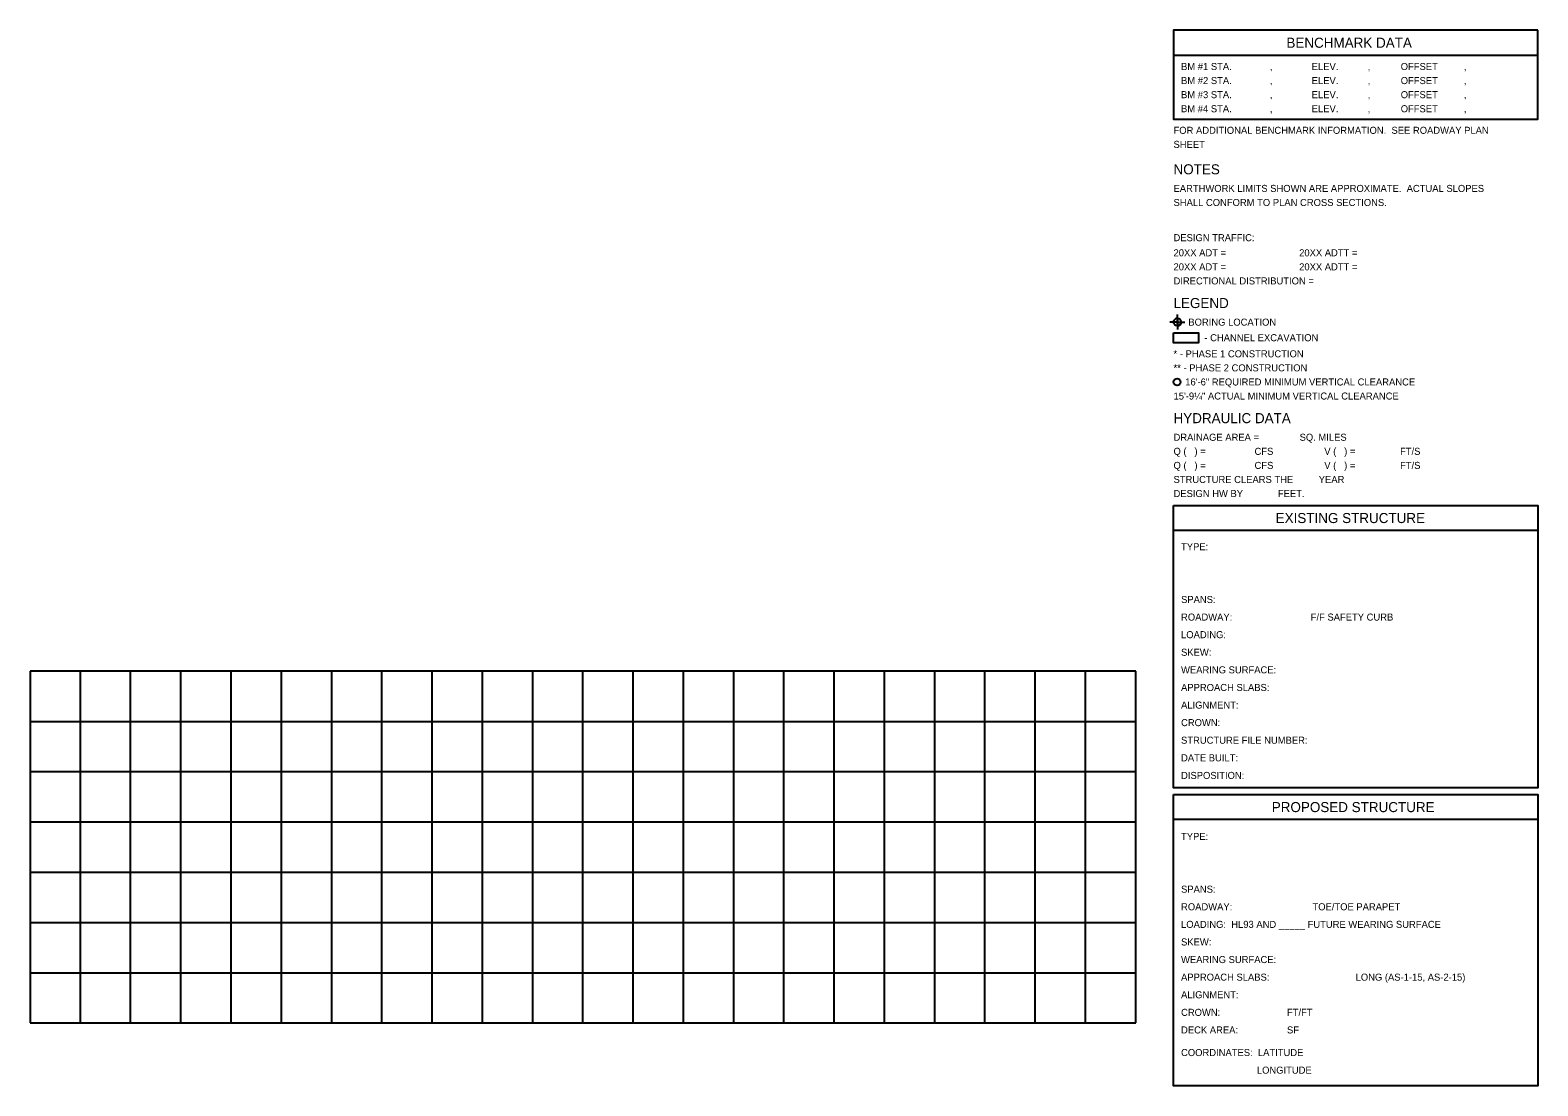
# Model space of a CAD drawing. Extents: x 0 to 112, y 0 to 22.
# Drawn here: x 81.7 to 111.7, y 0.5 to 21.5 of the extents above; entities that cross this region are included whole.
import ezdxf

# ---------------------------------------------------------------- set-up
doc = ezdxf.new("R2010")
doc.units = 0
for name, color, linetype in [('GT_Project_Soil_Boring', 7, 'Continuous'), ('SH_Data', 7, 'Continuous'), ('SH_Major_Grid_Line', 7, 'Continuous')]:
    doc.layers.add(name, color=color, linetype=linetype)

msp = doc.modelspace()

# ---------------------------------------------------------------- linework, layer by layer
at = {"layer": 'GT_Project_Soil_Boring'}
for p, q in [((104.529, 15.693), (104.379, 15.693)), ((104.529, 15.693), (104.454, 15.693)), ((104.529, 15.693), (104.529, 15.843)), ((104.529, 15.768), (104.529, 15.693)), ((104.529, 15.693), (104.529, 15.543)), ((104.529, 15.693), (104.679, 15.693)), ((104.529, 15.618), (104.529, 15.693)), ((104.529, 15.693), (104.604, 15.693))]:
    msp.add_line(p, q, dxfattribs=at)
msp.add_circle((104.529, 15.693), 0.075, dxfattribs=at)
for start, end in [(90, 180), (270, 360)]:
    msp.add_arc((104.529, 15.693), 0.075, start, end, dxfattribs=at)
at = {"layer": 'SH_Data'}
for p, q in [((104.452, 21), (111.702, 21)), ((111.702, 11.545), (104.452, 11.545)), ((81.7, 8.75), (81.7, 1.75)), ((103.7, 8.75), (81.7, 8.75)), ((103.7, 1.75), (103.7, 8.75)), ((111.702, 5.795), (104.452, 5.795)), ((81.7, 1.75), (103.7, 1.75))]:
    msp.add_line(p, q, dxfattribs=at)
for points in [[(111.702, 21.5), (104.452, 21.5), (104.452, 19.727), (111.702, 19.727)], [(104.452, 15.482), (104.952, 15.482), (104.952, 15.282), (104.452, 15.282)], [(104.452, 12.045), (111.702, 12.045), (111.702, 6.431), (104.452, 6.431)], [(104.452, 6.295), (111.702, 6.295), (111.702, 0.5), (104.452, 0.5)]]:
    msp.add_lwpolyline(points, close=True, dxfattribs=at)
msp.add_circle((104.522, 14.501), 0.07, dxfattribs=at)
at = {"layer": 'SH_Major_Grid_Line'}
for p, q in [((82.7, 1.75), (82.7, 8.75)), ((83.7, 1.75), (83.7, 8.75)), ((84.7, 1.75), (84.7, 8.75)), ((85.7, 1.75), (85.7, 8.75)), ((86.7, 1.75), (86.7, 8.75)), ((87.7, 1.75), (87.7, 8.75)), ((88.7, 1.75), (88.7, 8.75)), ((89.7, 1.75), (89.7, 8.75)), ((90.7, 1.75), (90.7, 8.75)), ((91.7, 1.75), (91.7, 8.75)), ((92.7, 1.75), (92.7, 8.75)), ((93.7, 1.75), (93.7, 8.75)), ((94.7, 1.75), (94.7, 8.75)), ((95.7, 1.75), (95.7, 8.75)), ((96.7, 1.75), (96.7, 8.75)), ((97.7, 1.75), (97.7, 8.75)), ((98.7, 1.75), (98.7, 8.75)), ((99.7, 1.75), (99.7, 8.75)), ((100.7, 1.75), (100.7, 8.75)), ((101.7, 1.75), (101.7, 8.75)), ((102.7, 1.75), (102.7, 8.75)), ((81.7, 7.75), (103.7, 7.75)), ((81.7, 6.75), (103.7, 6.75)), ((81.7, 5.75), (103.7, 5.75)), ((81.7, 4.75), (103.7, 4.75)), ((81.7, 3.75), (103.7, 3.75)), ((81.7, 2.75), (103.7, 2.75))]:
    msp.add_line(p, q, dxfattribs=at)

# ---------------------------------------------------------------- texts
at = {"layer": 'SH_Data'}
for s, height, p in [('BENCHMARK DATA', 0.2, (106.699, 21.15)), ('BM #1 STA.', 0.14, (104.602, 20.707)), ('         ,', 0.14, (105.902, 20.707)), ('ELEV.', 0.14, (107.202, 20.707)), ('       ,', 0.14, (107.952, 20.707)), ('OFFSET', 0.14, (108.973, 20.707)), ('      ,', 0.14, (109.917, 20.707)), ('BM #2 STA.', 0.14, (104.602, 20.427)), ('         ,', 0.14, (105.902, 20.427)), ('ELEV.', 0.14, (107.202, 20.427)), ('       ,', 0.14, (107.952, 20.427)), ('OFFSET', 0.14, (108.973, 20.427)), ('      ,', 0.14, (109.917, 20.427)), ('BM #3 STA.', 0.14, (104.602, 20.147)), ('         ,', 0.14, (105.902, 20.147)), ('ELEV.', 0.14, (107.202, 20.147)), ('       ,', 0.14, (107.952, 20.147)), ('OFFSET', 0.14, (108.973, 20.147)), ('      ,', 0.14, (109.917, 20.147)), ('BM #4 STA.', 0.14, (104.602, 19.867)), ('         ,', 0.14, (105.902, 19.867)), ('ELEV.', 0.14, (107.202, 19.867)), ('       ,', 0.14, (107.952, 19.867)), ('OFFSET', 0.14, (108.973, 19.867)), ('      ,', 0.14, (109.917, 19.867)), ('FOR ADDITIONAL BENCHMARK INFORMATION.  SEE ROADWAY PLAN', 0.14, (104.452, 19.438)), ('SHEET      ', 0.14, (104.452, 19.158)), ('NOTES', 0.2, (104.452, 18.632)), ('EARTHWORK LIMITS SHOWN ARE APPROXIMATE.  ACTUAL SLOPES', 0.14, (104.452, 18.282)), ('SHALL CONFORM TO PLAN CROSS SECTIONS.', 0.14, (104.452, 18.002)), ('DESIGN TRAFFIC:', 0.14, (104.452, 17.302)), ('20XX ADT =', 0.14, (104.452, 17.002)), ('20XX ADTT =', 0.14, (106.952, 17.002)), ('20XX ADT =', 0.14, (104.452, 16.722)), ('20XX ADTT =', 0.14, (106.952, 16.722)), ('DIRECTIONAL DISTRIBUTION =', 0.14, (104.452, 16.442)), ('LEGEND', 0.2, (104.452, 15.972)), ('BORING LOCATION', 0.14, (104.747, 15.622)), ('- CHANNEL EXCAVATION', 0.14, (105.066, 15.312)), ('* - PHASE 1 CONSTRUCTION', 0.14, (104.452, 14.992)), ('** - PHASE 2 CONSTRUCTION', 0.14, (104.452, 14.712)), ('HYDRAULIC DATA', 0.2, (104.452, 13.682)), ('DRAINAGE AREA =', 0.14, (104.452, 13.332)), ('SQ. MILES', 0.14, (106.961, 13.332)), ('Q (   ) =', 0.14, (104.452, 13.052)), ('Q (   ) =', 0.14, (104.452, 12.772)), ('      CFS', 0.14, (105.752, 13.052)), ('      CFS', 0.14, (105.752, 12.772)), ('V (   ) =', 0.14, (107.452, 13.052)), ('V (   ) =', 0.14, (107.452, 12.772)), ('    FT/S', 0.14, (108.752, 13.052)), ('    FT/S', 0.14, (108.752, 12.772)), ('STRUCTURE CLEARS THE', 0.14, (104.452, 12.492)), ('YEAR', 0.14, (107.342, 12.492)), ('DESIGN HW BY', 0.14, (104.452, 12.212)), ('FEET.', 0.14, (106.529, 12.212)), ('EXISTING STRUCTURE', 0.2, (106.485, 11.695)), ('TYPE:', 0.14, (104.602, 11.155)), ('SPANS:', 0.14, (104.602, 10.105)), ('F/F SAFETY CURB', 0.14, (107.182, 9.755)), ('ROADWAY:', 0.14, (104.602, 9.755)), ('LOADING:', 0.14, (104.602, 9.405)), ('SKEW:', 0.14, (104.602, 9.055)), ('WEARING SURFACE:', 0.14, (104.602, 8.705)), ('APPROACH SLABS:', 0.14, (104.602, 8.355)), ('ALIGNMENT:', 0.14, (104.602, 8.005)), ('CROWN:', 0.14, (104.602, 7.655)), ('STRUCTURE FILE NUMBER:', 0.14, (104.602, 7.305)), ('DATE BUILT:', 0.14, (104.602, 6.955)), ('DISPOSITION:', 0.14, (104.602, 6.605)), ('PROPOSED STRUCTURE', 0.2, (106.407, 5.945)), ('TYPE:', 0.14, (104.602, 5.392)), ('SPANS:', 0.14, (104.602, 4.342)), ('ROADWAY:', 0.14, (104.602, 3.992)), ('TOE/TOE PARAPET', 0.14, (107.217, 3.992)), ('LOADING:  HL93 AND _____ FUTURE WEARING SURFACE', 0.14, (104.602, 3.642)), ('SKEW:', 0.14, (104.602, 3.292)), ('WEARING SURFACE:', 0.14, (104.602, 2.942)), ('APPROACH SLABS:', 0.14, (104.602, 2.592)), ('LONG (AS-1-15, AS-2-15)', 0.14, (108.075, 2.592)), ('ALIGNMENT:', 0.14, (104.602, 2.242)), ('CROWN:', 0.14, (104.602, 1.892)), ('FT/FT', 0.14, (106.71, 1.892)), ('DECK AREA:', 0.14, (104.602, 1.542)), ('SF', 0.14, (106.71, 1.542)), ('COORDINATES:  LATITUDE', 0.14, (104.602, 1.092)), ('                             LONGITUDE', 0.14, (104.602, 0.742))]:
    msp.add_text(s, height=height, dxfattribs=at).set_placement(p)
for s, p in [('16\'-6" REQUIRED MINIMUM VERTICAL CLEARANCE', (104.685, 14.432)), ('15\'-9¼" ACTUAL MINIMUM VERTICAL CLEARANCE', (104.452, 14.152))]:
    msp.add_text(s, height=0.14, rotation=0, dxfattribs=at).set_placement(p)

doc.saveas('drawing.dxf')
